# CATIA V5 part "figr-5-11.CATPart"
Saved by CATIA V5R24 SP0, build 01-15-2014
Part number: Part1
Bounding box of the stored display mesh (mm): x 0 to 150, y -70 to 70, z -150 to 69.804
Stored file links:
  D:\KAVITA\CATIA V5-6R2014 Project_ Kavita\CATIA V5-6R2014_partfiles\Partfiles\c05_catia_v5-6r2014_prt\figr-5-11.CATPart
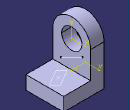
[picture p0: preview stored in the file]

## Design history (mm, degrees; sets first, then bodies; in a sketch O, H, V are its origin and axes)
Set1
  Sketch1 on face of Pad2, origin (0, 0, -100), H (1, 0, 0), V (0, 1, 0)
    point P1 (100, 0)
    coincidence: P1 H
  Sketch2 on face of Pad1, origin (50, 0, 0), H (0, 1, 0), V (0, 0, 1)
    line L1 (-40, -80) -> (40, -40)
  Plane1: type 1Line1Pt, RefPoint Sketch1, Line Sketch2
Body1 (main body)
  Sketch3 on yz-plane, origin (0, 0, 0), H (0, 1, 0), V (0, 0, 1)
    arc A1 centre (0, 0) radius 70 from (70, 0) to (-70, 0) ccw
    point P1 (70, 0)
    point P2 (-70, 0)
    line L1 (-70, 0) -> (-70, -150)
    line L2 (-70, -150) -> (70, -150)
    line L3 (70, -150) -> (70, 0)
    circle A2 centre (0, 0) radius 37.5
    radius A1 = 70
    radius A2 = 37.5
    distance O L2 = 150
    coincidence: P1 H, P2 H
    tangency: L1 A1, L3 A1
    horizontal: L2 H
  Pad1: profile Sketch3, direction (1, 0, 0), length 50
  Sketch4 on face of Pad1, origin (50, 0, 0), H (0, 1, 0), V (0, 0, 1)
    line L1 (-70, -150) -> (70, -150)
    line L2 (70, -150) -> (70, -100)
    line L3 (70, -100) -> (-70, -100)
    line L4 (-70, -100) -> (-70, -150)
    reference projected line E1 (-70, -150) -> (70, -150) from edge [face of Pad1 | face of Pad1]
    reference projected line E2 (-70, 0) -> (-70, -150) from edge [face of Pad1 | face of Pad1]
    reference projected line E3 (70, -150) -> (70, 0) from edge [face of Pad1 | face of Pad1]
    length L2 = 50
    horizontal: L1 H, L3 H
    vertical: L2 V, L4 V
    coincidence: L1 E1, E2 L4, L2 E3
  Pad2: profile Sketch4, direction (1, 0, 0), length 100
